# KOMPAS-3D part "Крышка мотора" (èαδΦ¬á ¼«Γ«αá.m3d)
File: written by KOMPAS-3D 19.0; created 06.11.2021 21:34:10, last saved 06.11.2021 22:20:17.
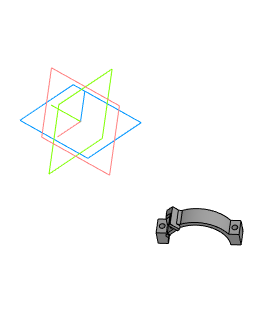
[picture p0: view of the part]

Document properties: Полное имя файла: D:\3D_print\3D проекты Компас 3D\Редуктор (Снова)\Крышка мотора.m3d

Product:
- Part/product: Крышка мотора
    Масса: 0.020193

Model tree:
1. Эскиз:1  (with: Элемент выдавливания:5)  (labels: Держатель мотора 36мм)
2. Элемент выдавливания:2  (with: Элемент выдавливания:6)  (labels: Держатель мотора 36мм)
     Расстояние 1 = -10
3. Эскиз:4  (with: Элемент выдавливания:2)
4. Элемент выдавливания:4  (with: Элемент выдавливания:8, Элемент выдавливания:6)
     Расстояние 1 = 1.64326; Расстояние 2 = 4.65674
5. Эскиз:5  (with: Элемент выдавливания:4, Элемент выдавливания:6)
6. Элемент выдавливания:5  (with: Элемент выдавливания:6)
     Расстояние 1 = 5; Расстояние 2 = 2
7. Эскиз:6  (with: Элемент выдавливания:2, Элемент выдавливания:13, Скругление:2)  (labels: Держатель мотора 36мм)
8. Элемент выдавливания:6
     Расстояние 1 = 7.93573; Расстояние 2 = 15.71
9. Эскиз:7  (with: Элемент выдавливания:2, Элемент выдавливания:5)
10. Элемент выдавливания:8
     Расстояние 1 = 9.43573
11. Эскиз:8  (with: Элемент выдавливания:4, Элемент выдавливания:6)
12. Элемент выдавливания:9
     Расстояние 2 = 37.883
13. Эскиз:11  (with: Элемент выдавливания:4, Элемент выдавливания:8, Элемент выдавливания:5, Элемент выдавливания:9)
14. Элемент выдавливания:11  (with: Элемент выдавливания:4)
     Расстояние 2 = 2
15. Эскиз:12  (with: Элемент выдавливания:4, Элемент выдавливания:11, Элемент выдавливания:8)
16. Элемент выдавливания:13
     Расстояние 1 = 5
17. Эскиз:13  (with: Элемент выдавливания:4, Элемент выдавливания:11, Элемент выдавливания:13)
18. Элемент выдавливания:14
     Расстояние 2 = 37.883
19. Скругление:1  (with: Элемент выдавливания:8)
     Радиус = 1
20. Скругление:2  (with: Элемент выдавливания:13)
     Радиус = 1
21. Скругление:3  (with: Элемент выдавливания:5)
     Радиус = 1
22. Скругление:4  (with: Элемент выдавливания:5)
     Радиус = 2

Referenced files in D:\3D_print\3D проекты Компас 3D\Редуктор (Снова)\: Намоточный станок (Projects 6).a3d
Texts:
  Щелевой оптический датчик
